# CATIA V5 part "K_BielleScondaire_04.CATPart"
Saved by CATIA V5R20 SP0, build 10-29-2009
Part number: Bielle_secondaire_04
Bounding box of the stored display mesh (mm): x -415 to 15, y -279.606 to -264.606, z -189.527 to -108.626
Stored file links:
  G:\Khaled_CFAO_2011\ST2M\ST2M_GR2\jcoetard\Khaled\CAD_CATIA\K_BielleScondaire_04.CATPart
  J:\Thinkmotion\Thinkmotion_COETARD\Maquette_catia\Maquette_catia_R20_Licence_education\jcharlescoetard.CATPRODUCT\Assemblage_Pince_Prehension_Mors_Paralleles.CATProduct
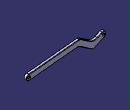
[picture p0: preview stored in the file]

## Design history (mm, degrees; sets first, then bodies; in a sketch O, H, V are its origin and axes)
Set1
  Plane1 "Plan_bielle_secondaire_03": linked copy from another document
  Point1: linked copy from another document
  Point2 "Point.9": linked copy from another document
Body1 (main body)
  Sketch1 on Plane1, origin (0, -279.606, 0), H (-1, 0, 0), V (0, 0, 1)
    construction line L1 (0, -140) -> (402.3828, -100.8463)
    construction line L2 (0, -150) -> (271.0207, -123.6257)
    point P4 (271.0207, -123.6257)
    line L3 (-1.4529, -135.0705) -> (269.5678, -108.6962)
    line L4 (252.5486, -140.4941) -> (1.4529, -164.9295)
    arc A1 centre (271.0207, -123.6257) radius 15 from (269.5678, -108.6962) to (279.5045, -111.2553) cw
    arc A2 centre (0, -150) radius 15 from (1.4529, -164.9295) to (-1.4529, -135.0705) cw
    reference projected point E1 (0, -150) from Point1
    construction line L5 (271.0207, -123.6257) -> (345.2427, -174.5284)
    point P8 (271.0207, -123.6257)
    point P9 (345.2427, -174.5284)
    line L6 (279.5045, -111.2553) -> (328.287, -144.7112)
    line L7 (336.7589, -186.8987) -> (279.0464, -147.3185)
    construction line L8 (345.2427, -174.5284) -> (400, -150)
    point P12 (345.2427, -174.5284)
    line L9 (367.2626, -148.2284) -> (393.8679, -136.3107)
    line L10 (406.1321, -163.6893) -> (351.3748, -188.2177)
    arc A3 centre (400, -150) radius 15 from (393.8679, -136.3107) to (406.1321, -163.6893) cw
    arc A4 centre (345.2427, -174.5284) radius 15 from (351.3748, -188.2177) to (336.7589, -186.8987) cw
    reference projected point E2 (400, -150) from Point2
    arc A5 centre (256.4229, -180.3061) radius 40 from (279.0464, -147.3185) to (252.5486, -140.4941) ccw
    point P19 (256.4229, -180.3061)
    arc A6 centre (350.9104, -111.7236) radius 40 from (367.2626, -148.2284) to (328.287, -144.7112) cw
    point P22 (350.9104, -111.7236)
    distance L3 L4 = 30
    distance L6 L7 = 30
    distance L9 L10 = 30
    length L8 = 60
    length L5 = 90
    radius A6 = 40
    radius A5 = 40
    distance P12 P22 = 63.06
    distance P8 P19 = 58.53
    tangency: A1 L3, A2 L3, A1 L4, A2 L4, A3 L9, A4 L9, A3 L10, A4 L10, A5 L7, A5 L4, A1 L6, A6 L9, A6 L6, A4 L7
    concentricity: A2 E1, A3 E2
    coincidence: P8 P4, P12 P9
  Pad1: profile Sketch1, direction (0, 1, 0), length 15
  Sketch2 on end face of Pad1, origin (0, -264.606, -140), H (1, 0, 0), V (0, 0, -1)
    point P1 (0, 10)
    reference projected point E1 (0, 10) from Point1
    coincidence: E1 P1
  Hole1: placed by Sketch2, at (0, -264.606, -150) direction (0, -1, 0), diameter 10, depth 20
  Sketch3 on end face of Pad1, origin (-400, -264.606, -140), H (1, 0, 0), V (0, 0, -1)
    point P1 (0, 10)
    reference projected point E1 (0, 10) from Point2
    coincidence: E1 P1
  Hole2: placed by Sketch3, at (-400, -264.606, -150) direction (0, -1, 0), diameter 10, depth 20
  Fillet1: radius 2, on start face of Pad1; end face of Pad1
